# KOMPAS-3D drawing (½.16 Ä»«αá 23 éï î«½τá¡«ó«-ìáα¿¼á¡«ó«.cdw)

Views: Вид 1, Вид 2
Referenced files: Подвеска ВЧ-заградителя.cdw
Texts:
  Текст на чертеже
  Размерные надписи
  Шероховатость
  Линия-выноска #1
  Линия-выноска #2
  Линия-выноска #3
  Отклонения формы и база
  Заголовок таблицы
  Ячейка таблицы
  Стрелка вида
  Обозначение изменения
  Фигурная скобка
  Номер узла
  Марка координационной оси
  VRCB
  Выносная надпись
  Обозначение узла
  Марка/позиционное обозначение с линией-выноской
  Марка/позиционное обозначение на линии
  Марка/позиционное обозначение без линии-выноски
  ООббыыччнныыйй
  Definition Term
  Definition List
  Address
  Blockquote
  Preformatted
  Courier New
  z-Bottom of Form
  z-Top of Form
  Лит-Масса-Масштаб
  Материал-Предприятие
  Title Specification
  Body Specification ( left align )
  Body Specificaton ( centered )
  Без имени
  SPEC
  Normal
  Txt
  Body Text
  heading 1
  Знак Знак Знак Знак Знак Знак
  Verdana
  Simplex
  TXT
  txt
  MS Sans Serif
  Additional DXF text style 0
  Обычный
  Термин
  Список определений
  Адрес
  Цитаты
  Форматированный
  Z-конец формы
  Z-начало формы
  ТекстШаг1
  Title
  Денис
  header
  heading 2
  AGOpus
  footer
  NormalParagraphStyle
  Body Text 3
  ссылки
  Подпись в квадратике
  табл
  цепи
  Маркировка
  клеммы, контакты
  тексты табл
  Тексты. 3,2
  ЗОНА_привяз
  текст переноса
  ТТееррммиинн
  ССппииссоокк ооппррееддееллеенниийй
  ААддрреесс
  ЦЦииттааттыы
  ФФооррммааттиирроовваанннныыйй
  Z-ккооннеецц ффооррммыы
  Z-ннааччааллоо ффооррммыы
  GOST 2.304 type A
  rustxt
  heading 8
  heading 3
  heading 6
  heading 7
  russ
  Абзац Знак
  heading 4
  heading 5
  heading 9
  HeliosLight
  Pa3
  Pa1
  Три с половиной
  style2
  Шрифт 2.5
  Заголовки
  RUSTXT
  Table Contents
  Table Heading
  ГОСТ_МНЕ
  ESK - Обозначение
  маркировка
  ISOCP
  ROMANS
  SIMPLEX
  Обычный (веб)
  Текст 3,5
  Tahoma
  CNBNDG+TimesNewRoman
  Subtitle
  ISOCPEUR
  FR5
  romans
  Подписи
  Схема монтажа ВЧ-заградителя на опору №23.
  Отпайка ВЛ-110 кВ Молчаново - Нариманово на ПС Липчинская
  Примечание - примечания см. 16/01-ПОС, л.10.
  Кран КС-35719-1-02
  подписи
  CONTINUOUS_RGB_0_0_0_THICK_0.13
  GOST2.303 4_RGB_0_0_0_SC_0.04_THICK_0.13
  CONTINUOUS_RGB_0_0_0_THICK_0.18
  CONTINUOUS_RGB_173_173_173_THICK_0.13
  GOST2.303 4_RGB_173_173_173_SC_0.04_THICK_0.13
  СONTINUOUS_RGB_0_0_0_THICK_0.13
  POLYLINE_STYLE_0.30_RGB_0_0_0
  CONTINUOUS_RGB_0_0_0_THICK_0.3
  GOST2.303 6_RGB_0_0_0_SC_0.04_THICK_0.13
  POLYLINE_STYLE_0.18_RGB_0_0_0
  GOST2.303 6_RGB_0_0_0_SC_0_THICK_0.18
  K5LT_AXLED_RGB_255_128_0_SC_1_THICK_0.18
  CONTINUOUS_RGB_0_0_0_THICK_0.25
  POLYLINE_STYLE_0.21_RGB_0_0_0
  СONTINUOUS_RGB_0_0_0_THICK_0.18
  POLYLINE_STYLE_0.50_RGB_0_0_0
  POLYLINE_STYLE_0.40_RGB_0_0_0
  CONTINUOUS_RGB_0_0_0_THICK_0.6
  Стили документа
  Автомобильный кран КС-35714
  Ромин
  Подвеска ВЧ-заградителя на
  опоре №23
  Политова
  Разраб.
  Микрюков
  Схема пневматическая соединений
  Перезавод ВЛ на ПС Тюмень. Реконструкция устройств
  РЗ и ПА на обратных концах отходящих ВЛ,
  ВОЛС Тюменского ТПО
  ВЛ-110 кВ Молчаново-Нариманово
  Нов.
  ГИП
  Матвеев
Dimensions and other numbers on the sheet: 16/01-ПОС; 7; 3,2_; 3.5; 2.5; 2,5; 1,8; 3,2; 2,5 (контакты, клеммы); 3,2 (надписи); 3,2 (Зоны); 5; 2,5_01; 2,5_3; 3,5_01; 3,5_tabl; 5_заголовок; 2,3_; 3,2_зона не привяз; 3,5; 3.2 маркировка; 3,2 элементы; 3,2 линия; 3,2 таблица; 2,5 грязносинь; 2.5 курсив; 2.5_Э5_надписи; 2.5_Э5_ссылки; 2.5_кабель; 3.2; 2.5 надписи; 3 и 5; 5,0_белый_подчёркнутый; 3.2 фиол; 3.2 (текст); 24600; 10500; 4000; 6100; 4800; 12; 4; 05.14; 16/01-05-091-ЭП-; 16; 3; 253-14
